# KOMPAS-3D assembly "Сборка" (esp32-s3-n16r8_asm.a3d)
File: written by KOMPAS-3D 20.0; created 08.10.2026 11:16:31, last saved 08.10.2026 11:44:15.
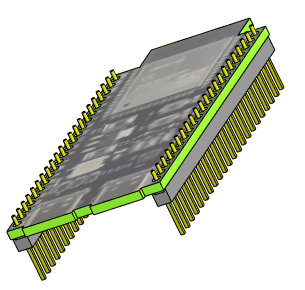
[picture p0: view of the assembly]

Document properties: Полное имя файла: D:\RicWork\Project-EPS32\box_compas\esp32\esp32-s3-n16r8_asm.a3d

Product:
- Part/product: Сборка
    Масса: 0.0251865
  - Component [detail]: Деталь  | Масса: 0.019451; source file: esp32-s3-n16r8.m3d
  - Component [detail]: Деталь  | qty 2  | Масса: 0.00286774; source file: ..\разъемы\pls_22.m3d

Referenced files in D:\RicWork\Project-EPS32\box_compas\esp32\: esp32-s3-n16r8.m3d
Referenced files in D:\RicWork\Project-EPS32\box_compas\разъемы\: pls_22.m3d
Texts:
  Деталь (1)
  Деталь (2)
